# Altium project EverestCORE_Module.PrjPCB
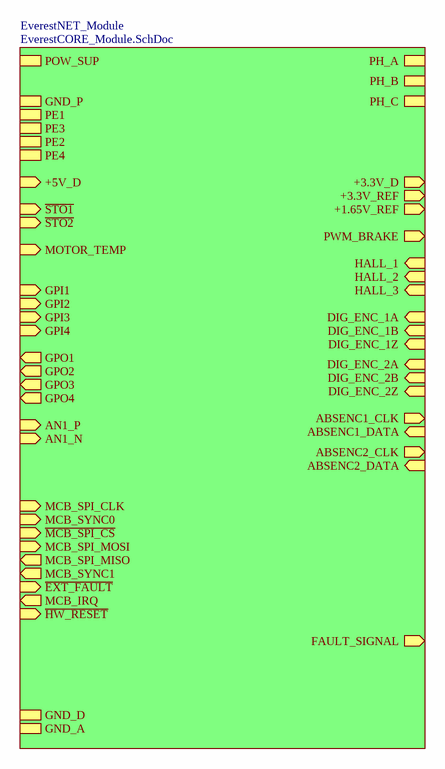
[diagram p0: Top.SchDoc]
2 sheets, 17 parts. Net scope: hierarchical (ports join the sheet entries above them; power ports are global).
Board file: EverestCORE_Module.PcbDoc
Sheets:
  Top.SchDoc
    EverestNET_Module = EverestCORE_Module.SchDoc

## Sheet Top.SchDoc: EVE-CORE
size A3; Organization: Ingenia Motion Control; Address1: Carrer Avila, 124, 2B; Address2: 08018 Barcelona Spain; Address3: www.ingeniamc.com; Address4: www.ingeniamc.com; Documentation: https://doc.ingeniamc.com/x/ZIPLBQ

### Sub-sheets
EverestNET_Module = EverestCORE_Module.SchDoc: MOTOR_TEMP (in), DIG_ENC_2A (in), DIG_ENC_1Z (in), AN1_N (in), DIG_ENC_2Z (in), HALL_1 (in), ~{STO1} (in), +5V_D (in), DIG_ENC_1A (in), PWM_BRAKE (out), GPO3 (out), ABSENC1_DATA (in), GPO1 (out), +3.3V_D (out), GPI2 (in), HALL_3 (in), HALL_2 (in), AN1_P (in), +3.3V_REF (out), ABSENC2_DATA (in), GPO4 (out), DIG_ENC_1B (in), DIG_ENC_2B (in), ABSENC1_CLK (out), PE1, GND_A, GPO2 (out), PH_A, PH_B, PH_C, ABSENC2_CLK (out), GPI3 (in), +1.65V_REF (out), GPI1 (in), PE2, FAULT_SIGNAL (out), POW_SUP, GND_P, ~{STO2} (in), GND_D, PE3, GPI4 (in), PE4, MCB_SPI_CLK (in), MCB_SYNC0 (in), ~{MCB_SPI_CS} (in), MCB_SPI_MOSI (in), MCB_SPI_MISO (out), MCB_SYNC1 (out), ~{EXT_FAULT} (in), MCB_IRQ (out), ~{HW_RESET} (in)

## Sheet EverestCORE_Module.SchDoc: EVE-CORE
size A3; Organization: Ingenia Motion Control; Address1: Carrer Avila, 124, 2B; Address2: 08018 Barcelona Spain; Address3: www.ingeniamc.com; Address4: www.ingeniamc.com; Revision: EVE-CORE-V6; Documentation: https://doc.ingeniamc.com/x/ZIPLBQ
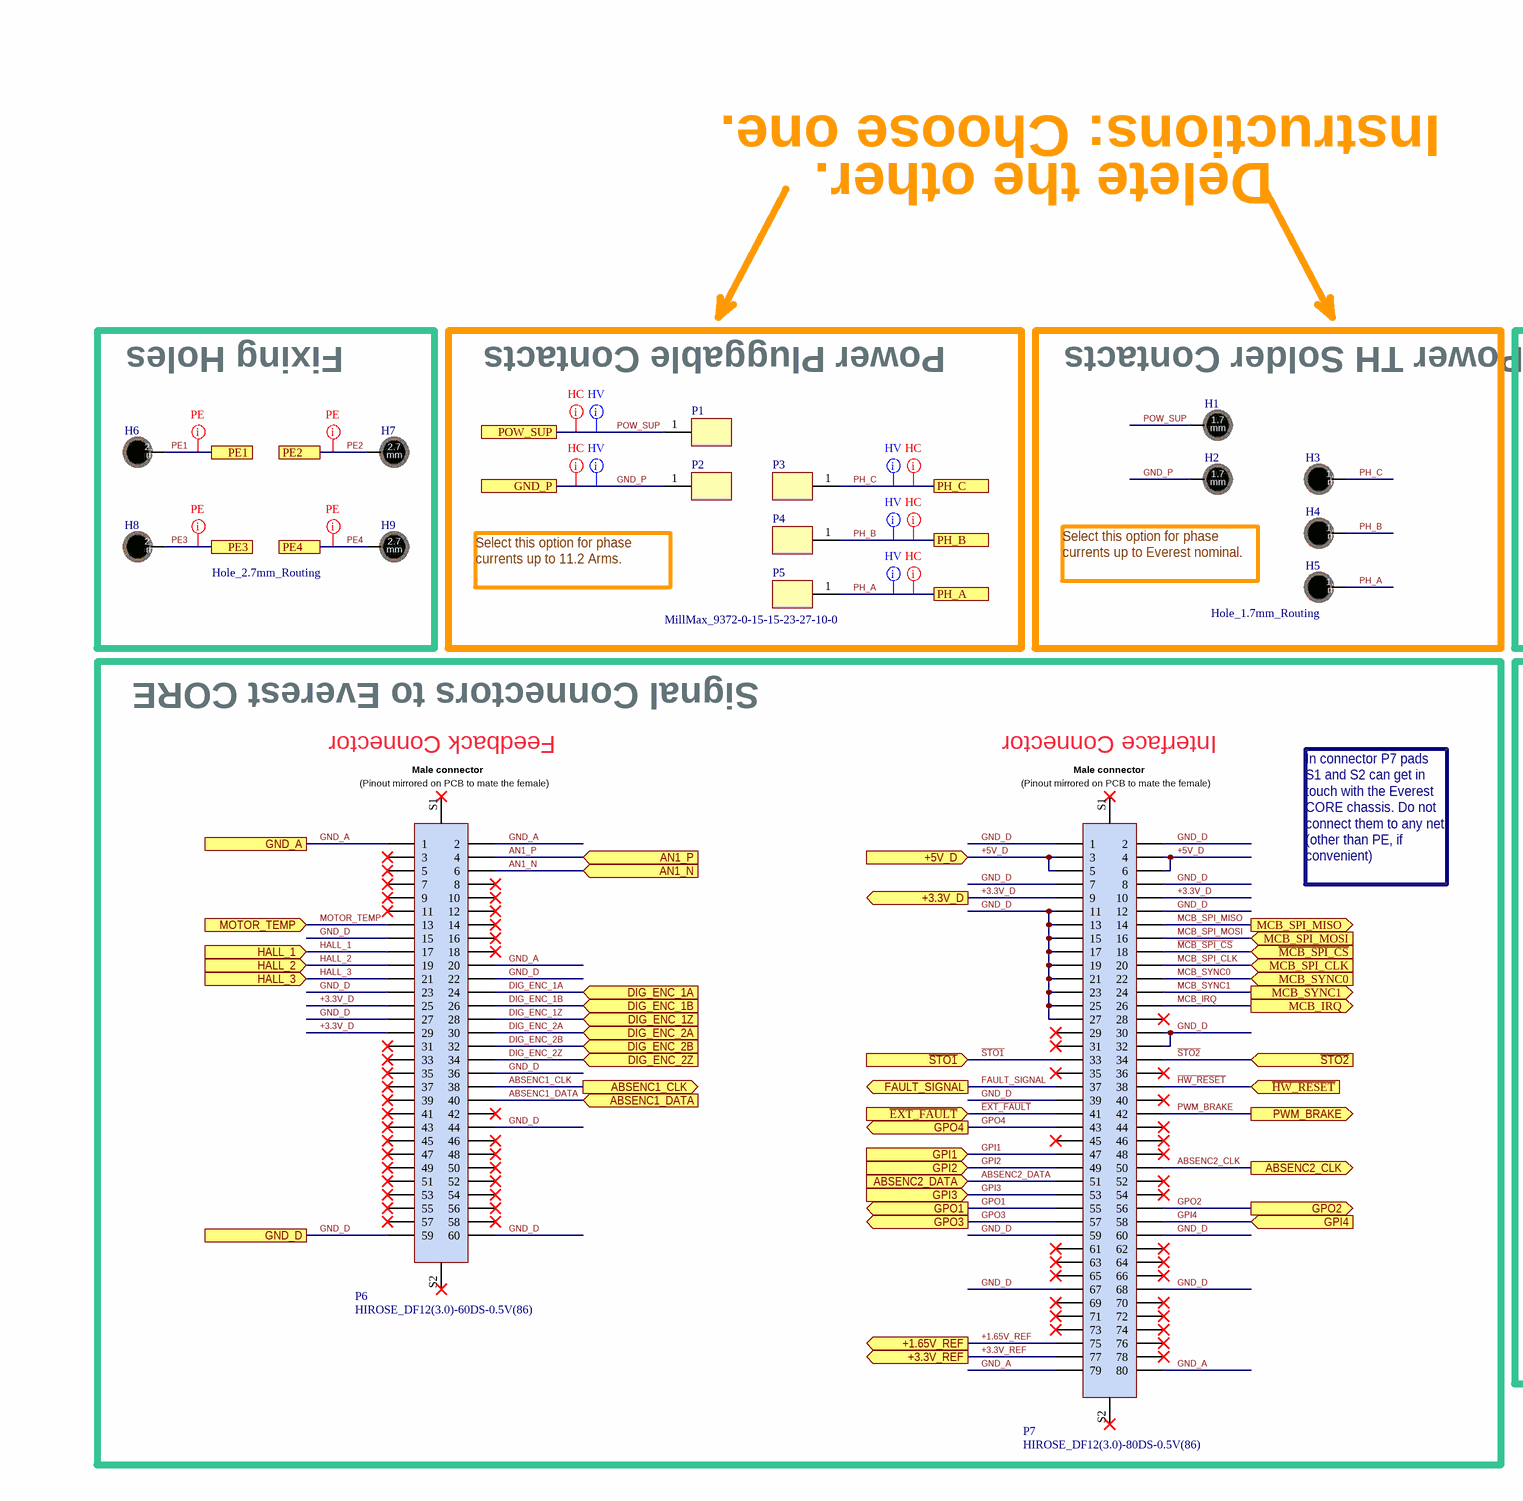
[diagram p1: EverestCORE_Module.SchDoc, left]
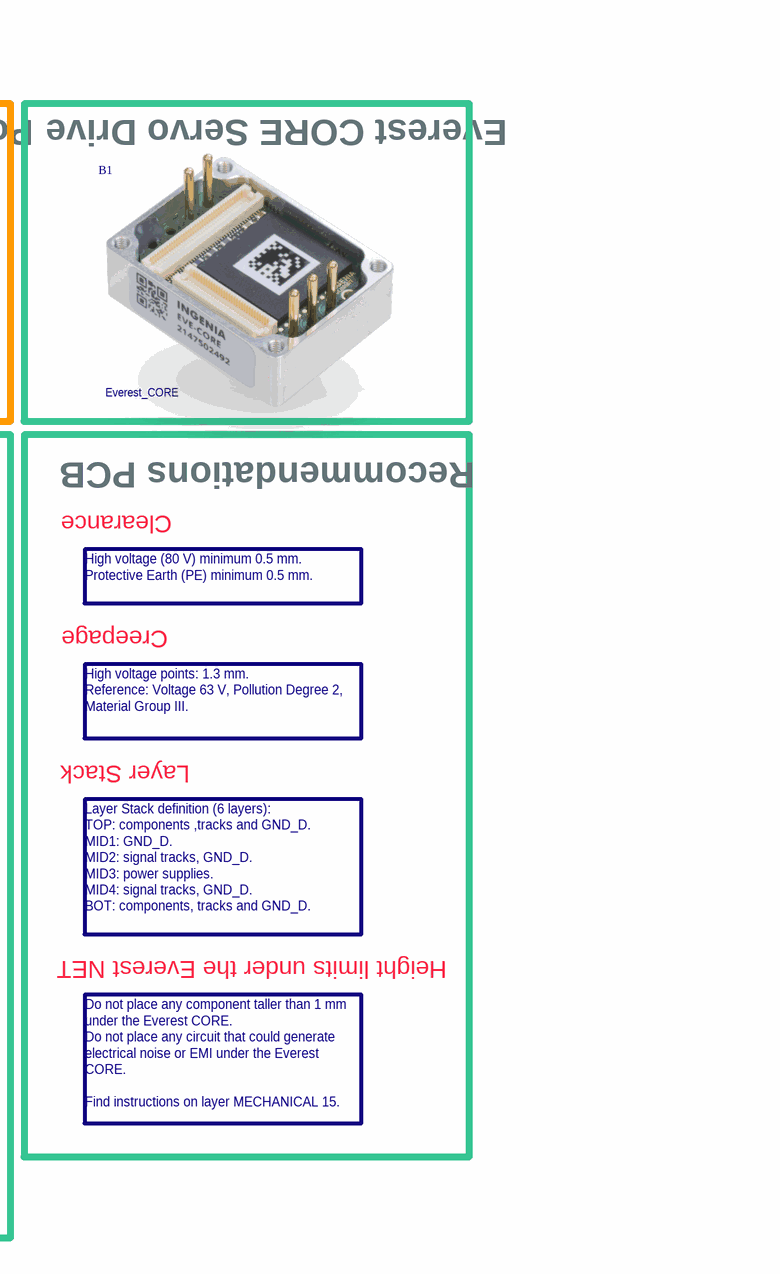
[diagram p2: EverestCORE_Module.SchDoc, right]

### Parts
B1  Everest_CORE  [EVEREST_CORE]
H1  (no value)  [Hole_1.7mm_Routing]  (no BOM)
H2  (no value)  [Hole_1.7mm_Routing]  (no BOM)
H3  (no value)  [Hole_1.7mm_Routing]  (no BOM)
H4  (no value)  [Hole_1.7mm_Routing]  (no BOM)
H5  (no value)  [Hole_1.7mm_Routing]  (no BOM)
H6  (no value)  [Hole_2.7mm_Routing]  (no BOM)
H7  (no value)  [Hole_2.7mm_Routing]  (no BOM)
H8  (no value)  [Hole_2.7mm_Routing]  (no BOM)
H9  (no value)  [Hole_2.7mm_Routing]  (no BOM)
P1  (no value)  [MillMax_9372-0-15-15-23-27-10-0_HD]
P2  (no value)  [MillMax_9372-0-15-15-23-27-10-0_HD]
P3  (no value)  [MillMax_9372-0-15-15-23-27-10-0_HD]
P4  (no value)  [MillMax_9372-0-15-15-23-27-10-0_HD]
P5  CompletePN: MillMax_9372-0-15-15-23-27-10-0  [MillMax_9372-0-15-15-23-27-10-0_HD]
P6  HIROSE_DF12(3.0)-60DS-0.5V(86)  [HIROSE_DF12(3.0)-60DS-0.5V(86)]
P7  HIROSE_DF12(3.0)-80DS-0.5V(86)  [HIROSE_DF12(3.0)-80DS-0.5V(86)]

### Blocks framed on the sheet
Fixing Holes: H6-H9
Power Pluggable Contacts: P1-P5
Power TH Solder Contacts: H1-H5
Everest CORE Servo Drive: B1
Signal Connectors to Everest CORE: P6 P7

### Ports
+1.65V_REF (out), +3.3V_D (out), +3.3V_REF (out), +5V_D (in), ABSENC1_CLK (out), ABSENC1_DATA (in), ABSENC2_CLK (out), ABSENC2_DATA (in), AN1_N (in), AN1_P (in), DIG_ENC_1A (in), DIG_ENC_1B (in), DIG_ENC_1Z (in), DIG_ENC_2A (in), DIG_ENC_2B (in), DIG_ENC_2Z (in), FAULT_SIGNAL (out), GND_A, GND_D, GND_P, GPI1 (in), GPI2 (in), GPI3 (in), GPI4 (in), GPO1 (out), GPO2 (out), GPO3 (out), GPO4 (out), HALL_1 (in), HALL_2 (in), HALL_3 (in), MCB_IRQ (out), MCB_SPI_CLK (in), MCB_SPI_MISO (out), MCB_SPI_MOSI (in), MCB_SYNC0 (in), MCB_SYNC1 (out), MOTOR_TEMP (in), PE1, PE2, PE3, PE4, PH_A, PH_B, PH_C, POW_SUP, PWM_BRAKE (out), ~{EXT_FAULT} (in), ~{HW_RESET} (in), ~{MCB_SPI_CS} (in), ~{STO1} (in), ~{STO2} (in)

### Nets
+1.65V_REF: P7.75 ; port +1.65V_REF
+3.3V_D: P6.25 P6.29 P7.9 P7.10 ; port +3.3V_D
+3.3V_REF: P7.77 ; port +3.3V_REF
+5V_D: P7.3 P7.4 P7.5 P7.6 ; port +5V_D
~{EXT_FAULT}: P7.41 ; port ~{EXT_FAULT}
~{HW_RESET}: P7.38 ; port ~{HW_RESET}
~{MCB_SPI_CS}: P7.18 ; port ~{MCB_SPI_CS}
~{STO1}: P7.33 ; port ~{STO1}
~{STO2}: P7.34 ; port ~{STO2}
ABSENC1_CLK: P6.38 ; port ABSENC1_CLK
ABSENC1_DATA: P6.40 ; port ABSENC1_DATA
ABSENC2_CLK: P7.50 ; port ABSENC2_CLK
ABSENC2_DATA: P7.51 ; port ABSENC2_DATA
AN1_N: P6.6 ; port AN1_N
AN1_P: P6.4 ; port AN1_P
DIG_ENC_1A: P6.24 ; port DIG_ENC_1A
DIG_ENC_1B: P6.26 ; port DIG_ENC_1B
DIG_ENC_1Z: P6.28 ; port DIG_ENC_1Z
DIG_ENC_2A: P6.30 ; port DIG_ENC_2A
DIG_ENC_2B: P6.32 ; port DIG_ENC_2B
DIG_ENC_2Z: P6.34 ; port DIG_ENC_2Z
FAULT_SIGNAL: P7.37 ; port FAULT_SIGNAL
GND_A: P6.1 P6.2 P6.20 P7.79 P7.80 ; port GND_A
GND_D: P6.15 P6.22 P6.23 P6.27 P6.36 P6.44 P6.59 P6.60 P7.1 P7.2 P7.7 P7.8 P7.11 P7.12 P7.13 P7.15 P7.17 P7.19 P7.21 P7.23 P7.25 P7.27 P7.30 P7.32 P7.39 P7.59 P7.60 P7.67 P7.68 ; port GND_D
GND_P: H2.1 P2.1 ; port GND_P
GPI1: P7.47 ; port GPI1
GPI2: P7.49 ; port GPI2
GPI3: P7.53 ; port GPI3
GPI4: P7.58 ; port GPI4
GPO1: P7.55 ; port GPO1
GPO2: P7.56 ; port GPO2
GPO3: P7.57 ; port GPO3
GPO4: P7.43 ; port GPO4
HALL_1: P6.17 ; port HALL_1
HALL_2: P6.19 ; port HALL_2
HALL_3: P6.21 ; port HALL_3
MCB_IRQ: P7.26 ; port MCB_IRQ
MCB_SPI_CLK: P7.20 ; port MCB_SPI_CLK
MCB_SPI_MISO: P7.14 ; port MCB_SPI_MISO
MCB_SPI_MOSI: P7.16 ; port MCB_SPI_MOSI
MCB_SYNC0: P7.22 ; port MCB_SYNC0
MCB_SYNC1: P7.24 ; port MCB_SYNC1
MOTOR_TEMP: P6.13 ; port MOTOR_TEMP
PE1: H6.1 ; port PE1
PE2: H7.1 ; port PE2
PE3: H8.1 ; port PE3
PE4: H9.1 ; port PE4
PH_A: H5.1 P5.1 ; port PH_A
PH_B: H4.1 P4.1 ; port PH_B
PH_C: H3.1 P3.1 ; port PH_C
POW_SUP: H1.1 P1.1 ; port POW_SUP
PWM_BRAKE: P7.42 ; port PWM_BRAKE

Not connected (* = marked no-connect by the designer): P6 3* 5* 7* 8* 9* 10* 11* 12* 14* 16* 18* 31* 33* 35* 37* 39* 41* 42* 43* 45* 46* 47* 48* 49* 50* 51* 52* 53* 54* 55* 56* 57* 58* S1(shield1)* S2(Shield2)*; P7 28* 29* 31* 35* 36* 40* 44* 45* 46* 48* 52* 54* 61* 62* 63* 64* 65* 66* 69* 70* 71* 72* 73* 74* 76* 78* S1(Shield2)* S2(Shield2)*

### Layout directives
net class ProtectiveEarth: PE1, PE2, PE3, PE4
net class HighCurrent: GND_P, PH_A, PH_B, PH_C, POW_SUP
net class HighVoltage: GND_P, PH_A, PH_B, PH_C, POW_SUP

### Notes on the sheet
- Instructions: Choose one.
- Delete the other.
- Select this option for phase currents up to Everest nominal.
- (near P2) Select this option for phase currents up to 11.2 Arms.
- Recommendations PCB
- Feedback Connector
- Interface Connector
- Clearance
- High voltage (80 V) minimum 0.5 mm.
  Protective Earth (PE) minimum 0.5 mm.
- Creepage
- In connector P7 pads S1 and S2 can get in touch with the Everest CORE chassis. Do not connect them to any net (other than PE, if convenient)
- High voltage points: 1.3 mm.
  Reference: Voltage 63 V, Pollution Degree 2, Material Group III.
- Layer Stack
- Layer Stack definition (6 layers):
  TOP: components ,tracks and GND_D.
  MID1: GND_D.
  MID2: signal tracks, GND_D.
  MID3: power supplies.
  MID4: signal tracks, GND_D.
  BOT: components, tracks and GND_D.
- Height limits under the Everest NET
- Do not place any component taller than 1 mm under the Everest CORE.
  Do not place any circuit that could generate electrical noise or EMI under the Everest CORE.
  Find instructions on layer MECHANICAL 15.

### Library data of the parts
B1 = EVEREST_CORE: Everest CORE high-performance Servo Drive from Ingenia Motion Control.; ManufacturerPN: EVE-CORE; IsPreferred: 0; IngeniaID: 4681; TemperatureMaxC: 85; TemperatureMinC: -40
H1-H5 = Hole_1.7mm_Routing: Mounting, plated hole, 1.7 mm diameter; ManufacturerName: Ingenia; IsPreferred: 0; IngeniaID: 4513
H6-H9 = Hole_2.7mm_Routing: Mounting, plated hole, 2.7 mm diameter; ManufacturerName: Ingenia; IsPreferred: 1; IsGeneric: 0; IngeniaID: 3160
P1-P4 = Header 1: 1pin, receptacle for MillMax 6142, pass-through; ManufacturerPN: 9372-0-15-15-23-27-10-0; CompletePN: MillMax_9372-0-15-15-23-27-10-0; IsPreferred: 0; IngeniaID: 3714; TemperatureMaxC: 125; TemperatureMinC: -55
P5 = Header 1: 1pin, receptacle for MillMax 6142, pass-through; ManufacturerPN: 9372-0-15-15-23-27-10-0; IsPreferred: 0; IngeniaID: 3714; TemperatureMaxC: 125; TemperatureMinC: -55
P6 = Header_30X2_MALE: Connector SMD Mezzanine, 60 ways, 0.5mm pitch, 3mm stack height. Male; ManufacturerName: Hirose; IsPreferred: 0; IngeniaID: 3207; TemperatureMaxC: 125; TemperatureMinC: -45
P7 = Header_40x2_MALE: Connector SMD Mezzanine, 80 ways, 0.5mm pitch, 3mm stack height. Male with metal fitting and boss; ManufacturerName: Hirose; IsPreferred: 1; IsGeneric: 0; IngeniaID: 3721; TemperatureMaxC: 125; TemperatureMinC: -45; MTBF55h: 176336644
